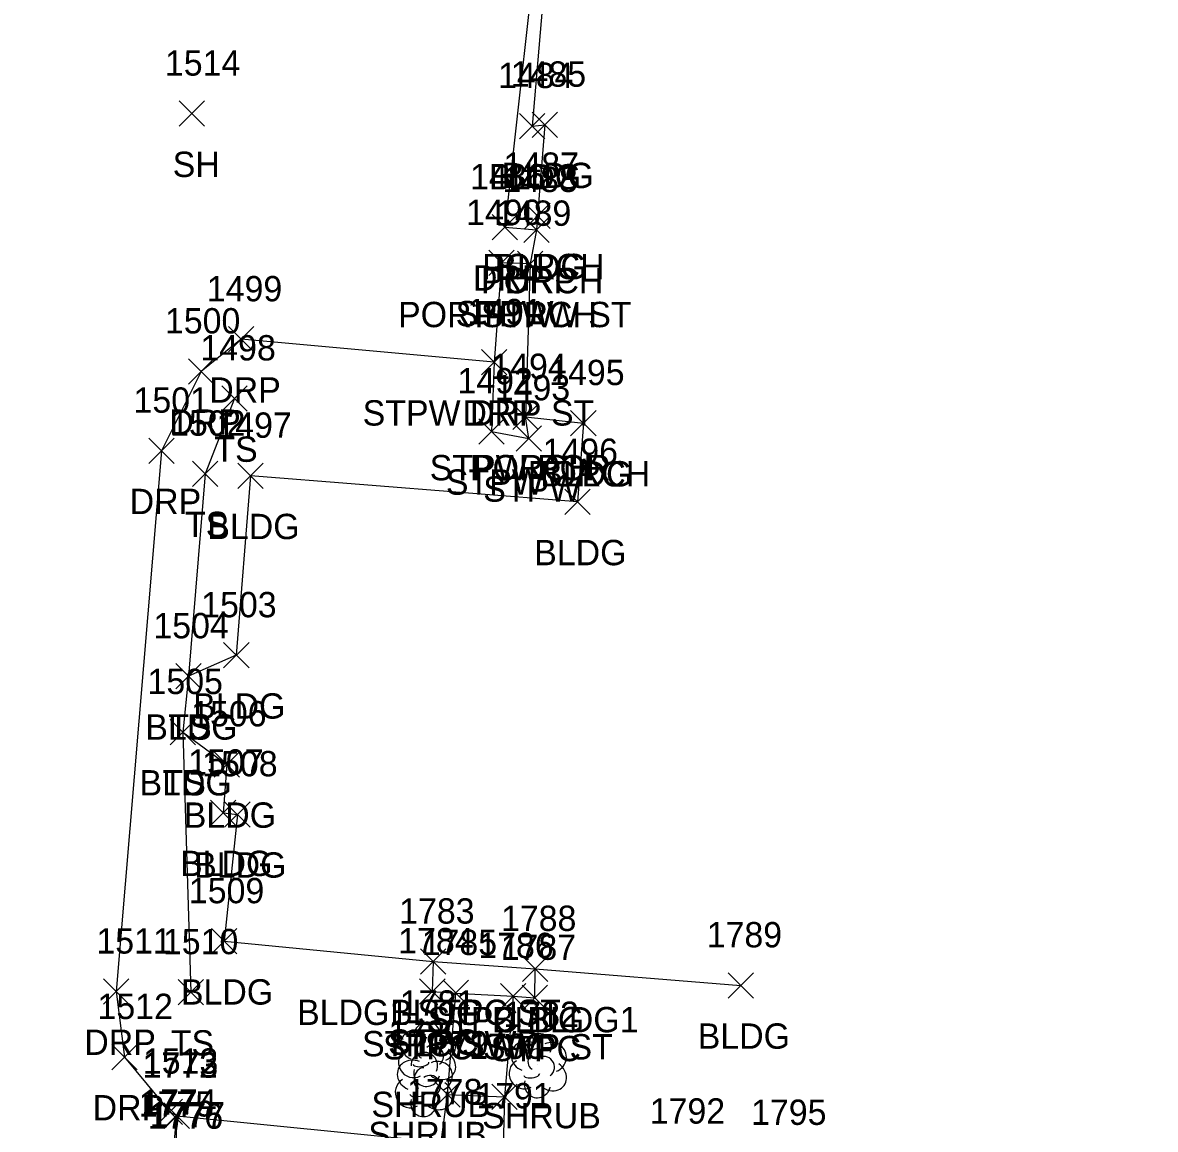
# Model space of a CAD drawing. Extents: x 1651305 to 1654558, y 539481 to 548441.
# Drawn here: x 1654395.2 to 1654484.6, y 544660.7 to 544748.1 of the extents above; entities that cross this region are included whole.
import ezdxf

# ---------------------------------------------------------------- set-up
doc = ezdxf.new("R2010")
doc.units = 0
for name, color, linetype in [('L_A', 7, 'Continuous'), ('L_I', 7, 'Continuous'), ('L_TIC', 7, 'Continuous'), ('LBC', 7, 'Continuous'), ('LBF', 7, 'Continuous'), ('LELB', 7, 'Continuous'), ('LSH', 7, 'Continuous'), ('R_A', 7, 'Continuous'), ('R_I', 7, 'Continuous'), ('R_TIC', 7, 'Continuous'), ('RDP', 7, 'Continuous'), ('RSW', 7, 'Continuous')]:
    doc.layers.add(name, color=color, linetype=linetype)

msp = doc.modelspace()

# ---------------------------------------------------------------- linework, layer by layer
at = {"layer": 'L_TIC'}
for points in [[(1654407.589, 544739.882), (1654409.589, 544741.882)], [(1654409.589, 544739.882), (1654407.589, 544741.882)], [(1654434.441, 544738.897), (1654436.441, 544740.897)], [(1654436.441, 544738.897), (1654434.441, 544740.897)], [(1654435.443, 544739.007), (1654437.443, 544741.007)], [(1654437.443, 544739.007), (1654435.443, 544741.007)], [(1654434.875, 544731.816), (1654436.875, 544733.816)], [(1654436.875, 544731.816), (1654434.875, 544733.816)], [(1654434.875, 544731.816), (1654436.875, 544733.816)], [(1654436.875, 544731.816), (1654434.875, 544733.816)], [(1654434.781, 544730.698), (1654436.781, 544732.698)], [(1654436.781, 544730.698), (1654434.781, 544732.698)], [(1654432.014, 544728.096), (1654434.014, 544730.096)], [(1654434.014, 544728.096), (1654432.014, 544730.096)], [(1654434.28, 544728.027), (1654436.28, 544730.027)], [(1654436.28, 544728.027), (1654434.28, 544730.027)], [(1654434.28, 544728.027), (1654436.28, 544730.027)], [(1654436.28, 544728.027), (1654434.28, 544730.027)], [(1654431.453, 544720.26), (1654433.453, 544722.26)], [(1654433.453, 544720.26), (1654431.453, 544722.26)], [(1654410.957, 544717.398), (1654412.957, 544719.398)], [(1654412.957, 544717.398), (1654410.957, 544719.398)], [(1654433.911, 544715.938), (1654435.911, 544717.938)], [(1654435.911, 544715.938), (1654433.911, 544717.938)], [(1654433.911, 544715.938), (1654435.911, 544717.938)], [(1654435.911, 544715.938), (1654433.911, 544717.938)], [(1654438.481, 544715.452), (1654440.481, 544717.452)], [(1654440.481, 544715.452), (1654438.481, 544717.452)], [(1654438.481, 544715.452), (1654440.481, 544717.452)], [(1654440.481, 544715.452), (1654438.481, 544717.452)], [(1654431.243, 544714.8), (1654433.243, 544716.8)], [(1654433.243, 544714.8), (1654431.243, 544716.8)], [(1654434.187, 544714.252), (1654436.187, 544716.252)], [(1654436.187, 544714.252), (1654434.187, 544716.252)], [(1654408.639, 544711.458), (1654410.639, 544713.458)], [(1654410.639, 544711.458), (1654408.639, 544713.458)], [(1654412.22, 544711.295), (1654414.22, 544713.295)], [(1654414.22, 544711.295), (1654412.22, 544713.295)], [(1654438.013, 544709.235), (1654440.013, 544711.235)], [(1654440.013, 544709.235), (1654438.013, 544711.235)], [(1654411.099, 544697.126), (1654413.099, 544699.126)], [(1654413.099, 544697.126), (1654411.099, 544699.126)], [(1654407.324, 544695.467), (1654409.324, 544697.467)], [(1654409.324, 544695.467), (1654407.324, 544697.467)], [(1654407.324, 544695.467), (1654409.324, 544697.467)], [(1654409.324, 544695.467), (1654407.324, 544697.467)], [(1654406.865, 544691.065), (1654408.865, 544693.065)], [(1654408.865, 544691.065), (1654406.865, 544693.065)], [(1654406.865, 544691.065), (1654408.865, 544693.065)], [(1654408.865, 544691.065), (1654406.865, 544693.065)], [(1654410.361, 544688.513), (1654412.361, 544690.513)], [(1654412.361, 544688.513), (1654410.361, 544690.513)], [(1654410.07, 544684.702), (1654412.07, 544686.702)], [(1654412.07, 544684.702), (1654410.07, 544686.702)], [(1654411.178, 544684.572), (1654413.178, 544686.572)], [(1654413.178, 544684.572), (1654411.178, 544686.572)], [(1654410.135, 544674.554), (1654412.135, 544676.554)], [(1654412.135, 544674.554), (1654410.135, 544676.554)], [(1654426.642, 544672.945), (1654428.642, 544674.945)], [(1654428.642, 544672.945), (1654426.642, 544674.945)], [(1654426.642, 544672.945), (1654428.642, 544674.945)], [(1654428.642, 544672.945), (1654426.642, 544674.945)], [(1654434.677, 544672.367), (1654436.677, 544674.367)], [(1654436.677, 544672.367), (1654434.677, 544674.367)], [(1654434.677, 544672.367), (1654436.677, 544674.367)], [(1654436.677, 544672.367), (1654434.677, 544674.367)], [(1654407.518, 544670.531), (1654409.518, 544672.531)], [(1654409.518, 544670.531), (1654407.518, 544672.531)], [(1654426.565, 544670.599), (1654428.565, 544672.599)], [(1654428.565, 544670.599), (1654426.565, 544672.599)], [(1654428.416, 544670.469), (1654430.416, 544672.469)], [(1654430.416, 544670.469), (1654428.416, 544672.469)], [(1654450.916, 544671.071), (1654452.916, 544673.071)], [(1654452.916, 544671.071), (1654450.916, 544673.071)], [(1654432.938, 544670.225), (1654434.938, 544672.225)], [(1654434.938, 544670.225), (1654432.938, 544672.225)], [(1654434.653, 544670.086), (1654436.653, 544672.086)], [(1654436.653, 544670.086), (1654434.653, 544672.086)]]:
    msp.add_lwpolyline(points, dxfattribs=at)
at = {"layer": 'LBC'}
for points in [[(1654459.451, 544756.754), (1654437.049, 544758.713), (1654435.441, 544739.897), (1654436.443, 544740.007), (1654435.875, 544732.816)], [(1654439.481, 544716.452), (1654439.013, 544710.235), (1654413.22, 544712.295), (1654412.099, 544698.126), (1654408.324, 544696.467), (1654407.865, 544692.065), (1654411.361, 544689.513), (1654411.07, 544685.702), (1654412.178, 544685.572), (1654411.135, 544675.554), (1654427.642, 544673.945), (1654435.677, 544673.367), (1654451.916, 544672.071)]]:
    msp.add_lwpolyline(points, dxfattribs=at)
at = {"layer": 'LBF'}
for points in [[(1654435.875, 544732.816), (1654435.781, 544731.698), (1654435.28, 544729.027), (1654434.911, 544716.938), (1654439.481, 544716.452)], [(1654435.28, 544729.027), (1654433.014, 544729.096), (1654432.453, 544721.26), (1654432.243, 544715.8), (1654435.187, 544715.252), (1654434.911, 544716.938)], [(1654427.642, 544673.945), (1654427.565, 544671.599), (1654429.416, 544671.469), (1654433.938, 544671.225), (1654435.653, 544671.086), (1654435.677, 544673.367)]]:
    msp.add_lwpolyline(points, dxfattribs=at)
at = {"layer": 'LELB'}
for points in [[(1654411.957, 544718.398), (1654409.639, 544712.458), (1654408.324, 544696.467)], [(1654407.865, 544692.065), (1654408.518, 544671.531)]]:
    msp.add_lwpolyline(points, dxfattribs=at)
at = {"layer": 'LSH'}
for p, q in [((1654427.13, 544666.678), (1654427.13, 544666.678)), ((1654427.13, 544666.678), (1654427.13, 544666.678)), ((1654435.872, 544665.791), (1654435.872, 544665.791)), ((1654435.872, 544665.791), (1654435.872, 544665.791)), ((1654426.883, 544664.302), (1654426.883, 544664.302)), ((1654426.883, 544664.302), (1654426.883, 544664.302))]:
    msp.add_line(p, q, dxfattribs=at)
for centre in [(1654427.177, 544668.112), (1654435.919, 544667.225), (1654426.93, 544665.736)]:
    msp.add_arc(centre, 1.047, 335.52715, 180.95627, dxfattribs=at)
for centre, major_axis, ratio, start_param, end_param in [((1654426.339, 544667.344), (1.21, -0.512), 0.895232, 1.570796, 4.712389), ((1654426.922, 544667.136), (-0.208, -0.792), 0.645439, 3.141593, 6.283185), ((1654428.172, 544667.261), (-1.141, -0.483), 0.949671, 1.570796, 4.712389), ((1654435.081, 544666.457), (1.21, -0.512), 0.895232, 1.570796, 4.712389), ((1654426.047, 544665.969), (0.584, -1.042), 0.959034, 3.141593, 6.283185), ((1654427.63, 544666.511), (-0.5, 0.667), 0.989748, 3.141593, 6.283185), ((1654435.664, 544666.249), (-0.208, -0.792), 0.645439, 3.141593, 6.283185), ((1654436.914, 544666.374), (-1.141, -0.483), 0.949671, 1.570796, 4.712389), ((1654426.091, 544664.968), (1.21, -0.512), 0.895232, 1.570796, 4.712389), ((1654428.131, 544665.845), (-1.09, 0.792), 0.841452, 1.570796, 4.712389), ((1654427.925, 544664.885), (-1.141, -0.483), 0.949671, 1.570796, 4.712389), ((1654434.789, 544665.082), (0.584, -1.042), 0.959034, 3.141593, 6.283185), ((1654436.372, 544665.624), (-0.5, 0.667), 0.989748, 3.141593, 6.283185), ((1654427.131, 544665.178), (0.265, 1.061), 0.942809, 1.570796, 4.712389), ((1654426.672, 544665.928), (-0.625, -0.083), 0.423636, 0, 3.141593), ((1654426.675, 544664.76), (-0.208, -0.792), 0.645439, 3.141593, 6.283185), ((1654436.873, 544664.958), (-1.09, 0.792), 0.841452, 1.570796, 4.712389), ((1654425.8, 544663.593), (0.584, -1.042), 0.959034, 3.141593, 6.283185), ((1654427.383, 544664.135), (-0.5, 0.667), 0.989748, 3.141593, 6.283185), ((1654427.883, 544663.469), (-1.09, 0.792), 0.841452, 1.570796, 4.712389), ((1654435.873, 544664.291), (0.265, 1.061), 0.942809, 1.570796, 4.712389), ((1654435.414, 544665.041), (-0.625, -0.083), 0.423636, 0, 3.141593), ((1654426.425, 544663.552), (-0.625, -0.083), 0.423636, 0, 3.141593), ((1654426.883, 544662.802), (0.265, 1.061), 0.942809, 1.570796, 4.712389)]:
    msp.add_ellipse(centre, major_axis=major_axis, ratio=ratio, start_param=start_param, end_param=end_param, dxfattribs=at)
at = {"layer": 'R_TIC'}
for points in [[(1654432.285, 544730.908), (1654434.285, 544732.908)], [(1654434.285, 544730.908), (1654432.285, 544732.908)], [(1654434.781, 544730.698), (1654436.781, 544732.698)], [(1654436.781, 544730.698), (1654434.781, 544732.698)], [(1654411.473, 544722.068), (1654413.473, 544724.068)], [(1654413.473, 544722.068), (1654411.473, 544724.068)], [(1654408.324, 544719.532), (1654410.324, 544721.532)], [(1654410.324, 544719.532), (1654408.324, 544721.532)], [(1654431.453, 544720.26), (1654433.453, 544722.26)], [(1654433.453, 544720.26), (1654431.453, 544722.26)], [(1654405.192, 544713.273), (1654407.192, 544715.273)], [(1654407.192, 544713.273), (1654405.192, 544715.273)], [(1654401.612, 544670.581), (1654403.612, 544672.581)], [(1654403.612, 544670.581), (1654401.612, 544672.581)], [(1654428.416, 544670.469), (1654430.416, 544672.469)], [(1654430.416, 544670.469), (1654428.416, 544672.469)], [(1654432.938, 544670.225), (1654434.938, 544672.225)], [(1654434.938, 544670.225), (1654432.938, 544672.225)], [(1654402.27, 544665.414), (1654404.27, 544667.414)], [(1654404.27, 544665.414), (1654402.27, 544667.414)], [(1654427.758, 544662.459), (1654429.758, 544664.459)], [(1654429.758, 544662.459), (1654427.758, 544664.459)], [(1654427.758, 544662.459), (1654429.758, 544664.459)], [(1654429.758, 544662.459), (1654427.758, 544664.459)], [(1654432.255, 544662.27), (1654434.255, 544664.27)], [(1654434.255, 544662.27), (1654432.255, 544664.27)], [(1654432.255, 544662.27), (1654434.255, 544664.27)], [(1654434.255, 544662.27), (1654432.255, 544664.27)], [(1654405.853, 544661.099), (1654407.853, 544663.099)], [(1654407.853, 544661.099), (1654405.853, 544663.099)], [(1654406.381, 544660.789), (1654408.381, 544662.789)], [(1654408.381, 544660.789), (1654406.381, 544662.789)], [(1654406.404, 544660.775), (1654408.404, 544662.775)], [(1654408.404, 544660.775), (1654406.404, 544662.775)], [(1654406.404, 544660.775), (1654408.404, 544662.775)], [(1654408.404, 544660.775), (1654406.404, 544662.775)]]:
    msp.add_lwpolyline(points, dxfattribs=at)
at = {"layer": 'RDP'}
for points in [[(1654484.618, 544797.687), (1654477.598, 544805.314), (1654468.622, 544807.803), (1654441.87, 544807.936), (1654423.668, 544807.277), (1654417.258, 544803.535), (1654413.711, 544798.668), (1654412.016, 544791.945), (1654410.65, 544766.459), (1654412.478, 544763.445), (1654416.611, 544760.995), (1654436.257, 544758.686), (1654433.285, 544731.908), (1654435.781, 544731.698)], [(1654432.453, 544721.26), (1654412.473, 544723.068), (1654409.324, 544720.532), (1654406.192, 544714.273), (1654402.612, 544671.581), (1654403.27, 544666.414), (1654406.853, 544662.099), (1654407.381, 544661.789), (1654407.089, 544658.718), (1654407.855, 544657.75), (1654443.015, 544654.447), (1654438.677, 544619.923), (1654433.469, 544580.157), (1654430.086, 544554.066), (1654427.975, 544537.224), (1654424.616, 544512.8), (1654419.649, 544473.553), (1654406.951, 544466.687)]]:
    msp.add_lwpolyline(points, dxfattribs=at)
at = {"layer": 'RSW'}
for points in [[(1654428.758, 544663.459), (1654429.416, 544671.469)], [(1654433.938, 544671.225), (1654433.255, 544663.27)], [(1654407.404, 544661.775), (1654428.256, 544659.691), (1654428.758, 544663.459), (1654433.255, 544663.27), (1654433.16, 544659.367), (1654447.415, 544658.156), (1654442.622, 544619.191), (1654446.363, 544618.839), (1654446.1, 544614.473), (1654442.009, 544614.425), (1654437.441, 544579.484), (1654433.815, 544552.684), (1654432.002, 544537.927), (1654429.103, 544516.836), (1654432.209, 544516.446), (1654440.587, 544515.607)], [(1654407.404, 544661.775), (1654407.293, 544658.868), (1654407.962, 544657.877), (1654443.269, 544654.592), (1654438.81, 544619.894), (1654433.558, 544580.17), (1654430.136, 544553.995), (1654428.025, 544537.281), (1654424.833, 544512.838), (1654419.77, 544473.615), (1654412.659, 544419.662), (1654404.122, 544354.774), (1654402.102, 544339.773), (1654395.487, 544286.058), (1654394.013, 544276.122), (1654388.386, 544229.583), (1654383.891, 544196.376), (1654382.201, 544184.333), (1654378.352, 544149.148), (1654372.361, 544105.495), (1654368.546, 544072.052)]]:
    msp.add_lwpolyline(points, dxfattribs=at)

# ---------------------------------------------------------------- texts
at = {"layer": 'L_A'}
for s, p in [('SH', (1654407.077, 544735.882)), ('BLDG', (1654432.031, 544734.897)), ('BLDG', (1654433.033, 544735.007)), ('PORCH', (1654431.497, 544727.816)), ('BLDG', (1654432.466, 544727.816)), ('PORCH', (1654431.403, 544726.698)), ('POR STPW ST', (1654424.863, 544724.027)), ('STPW', (1654429.408, 544724.096)), ('PORCH', (1654430.902, 544724.027)), ('STPW DRP ST', (1654422.067, 544716.26)), ('TS', (1654410.367, 544713.398)), ('STPW POR', (1654427.36, 544711.938)), ('PORCH', (1654430.533, 544711.938)), ('PORCH', (1654435.103, 544711.452)), ('BLDG', (1654436.072, 544711.452)), ('STPW', (1654428.637, 544710.8)), ('STPW', (1654431.58, 544710.252)), ('TS', (1654408.049, 544707.458)), ('BLDG', (1654409.81, 544707.295)), ('BLDG', (1654435.603, 544705.235)), ('BLDG', (1654408.69, 544693.126)), ('BLDG', (1654404.915, 544691.467)), ('TS', (1654406.734, 544691.467)), ('BLDG', (1654404.455, 544687.065)), ('TS', (1654406.274, 544687.065)), ('BLDG', (1654407.951, 544684.513)), ('BLDG', (1654407.66, 544680.702)), ('BLDG', (1654408.769, 544680.572)), ('BLDG', (1654407.725, 544670.554)), ('BLDG1 STPC ST', (1654416.894, 544668.945)), ('BLDG', (1654424.232, 544668.945)), ('STPC BLDG1', (1654427.188, 544668.367)), ('BLDG', (1654432.267, 544668.367)), ('BLDG', (1654448.507, 544667.071)), ('TS', (1654406.927, 544666.531)), ('STPC SWP', (1654422.023, 544666.469)), ('STPC SWP ST', (1654423.678, 544666.225)), ('STPC', (1654424.077, 544666.599)), ('STPC', (1654432.165, 544666.086)), ('SHRUB', (1654422.76, 544661.678)), ('SHRUB', (1654431.502, 544660.791)), ('SHRUB', (1654422.513, 544659.302))]:
    msp.add_text(s, height=2, dxfattribs=at).set_placement(p)
at = {"layer": 'L_I'}
for s, p in [('1514', (1654406.463, 544743.882)), ('1484', (1654432.748, 544742.897)), ('1485', (1654433.75, 544743.007)), ('1487', (1654433.182, 544735.816)), ('1487', (1654433.182, 544735.816)), ('1488', (1654433.089, 544734.698)), ('1490', (1654430.235, 544732.096)), ('1489', (1654432.58, 544732.027)), ('1489', (1654432.58, 544732.027)), ('1491', (1654430.327, 544724.26)), ('1498', (1654409.265, 544721.398)), ('1494', (1654432.219, 544719.938)), ('1494', (1654432.219, 544719.938)), ('1495', (1654436.788, 544719.452)), ('1495', (1654436.788, 544719.452)), ('1492', (1654429.55, 544718.8)), ('1493', (1654432.494, 544718.252)), ('1502', (1654406.868, 544715.458)), ('1497', (1654410.527, 544715.295)), ('1496', (1654436.265, 544713.235)), ('1503', (1654409.328, 544701.126)), ('1504', (1654405.553, 544699.467)), ('1504', (1654405.553, 544699.467)), ('1505', (1654405.093, 544695.065)), ('1505', (1654405.093, 544695.065)), ('1506', (1654408.534, 544692.513)), ('1507', (1654408.298, 544688.702)), ('1508', (1654409.407, 544688.572)), ('1509', (1654408.355, 544678.554)), ('1783', (1654424.949, 544676.945)), ('1783', (1654424.949, 544676.945)), ('1788', (1654432.984, 544676.367)), ('1788', (1654432.984, 544676.367)), ('1789', (1654449.215, 544675.071)), ('1510', (1654406.306, 544674.531)), ('1784', (1654424.873, 544674.599)), ('1785', (1654426.724, 544674.469)), ('1786', (1654431.19, 544674.225)), ('1787', (1654432.961, 544674.086)), ('1781', (1654425.005, 544669.678)), ('1782', (1654433.18, 544668.791)), ('1780', (1654424.104, 544667.302)), ('1795', (1654452.719, 544661.057))]:
    msp.add_text(s, height=2, dxfattribs=at).set_placement(p)
at = {"layer": 'R_A'}
for s, p in [('DRP', (1654430.774, 544726.908)), ('DRP', (1654433.27, 544726.698)), ('DRP', (1654409.962, 544718.068)), ('DRP', (1654429.941, 544716.26)), ('DRP', (1654406.812, 544715.532)), ('DRP', (1654403.681, 544709.273)), ('DRP', (1654400.101, 544666.581)), ('STPC SWP', (1654422.023, 544666.469)), ('STPC SWP ST', (1654423.678, 544666.225)), ('DRP', (1654400.758, 544661.414))]:
    msp.add_text(s, height=2, dxfattribs=at).set_placement(p)
at = {"layer": 'R_I'}
for s, p in [('1486', (1654430.538, 544734.908)), ('1488', (1654433.089, 544734.698)), ('1499', (1654409.773, 544726.068)), ('1491', (1654430.327, 544724.26)), ('1500', (1654406.466, 544723.532)), ('1501', (1654403.988, 544717.273)), ('1511', (1654401.054, 544674.581)), ('1785', (1654426.724, 544674.469)), ('1786', (1654431.19, 544674.225)), ('1512', (1654401.145, 544669.414)), ('1779', (1654426.057, 544666.459)), ('1779', (1654426.057, 544666.459)), ('1790', (1654430.476, 544666.27)), ('1790', (1654430.476, 544666.27)), ('1513', (1654404.727, 544665.099)), ('1772', (1654404.688, 544664.789)), ('1773', (1654404.712, 544664.775)), ('1773', (1654404.712, 544664.775)), ('1778', (1654425.563, 544662.691)), ('1791', (1654431.034, 544662.367)), ('1775', (1654404.396, 544661.718)), ('1774', (1654404.6, 544661.868)), ('1776', (1654405.108, 544660.75)), ('1777', (1654405.269, 544660.877)), ('1792', (1654444.722, 544661.156))]:
    msp.add_text(s, height=2, dxfattribs=at).set_placement(p)

doc.saveas('drawing.dxf')
